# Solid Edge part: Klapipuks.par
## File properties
Author: Türk
Template: Iso Part.par
Last saved by: Türk
Revision: 10
Application: Solid Edge
Accuracy: 0,990
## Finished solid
Body 1: solid body, 13 faces, 23 edges, 12 vertices.
  Faces by surface: plane 7, cone 3, cylinder 3
  Edges by curve: line 14, circle 9
Bounding box of the edges (mm): 22.000 x 10.000 x 33.000, from (-11, 0, -11) to (11, 10, 22).
Cylindrical faces by radius (mm): R10 x1, R11 x2
Conical faces (half-angle, radius in mm at the cone's reference point): 45 deg R10 x1, 45 deg R10.5 x2
Planar faces by outward normal: +x 1, +y 1, -x 1, -y 2, oblique 2
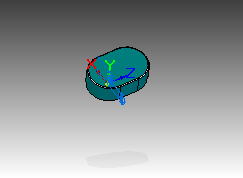
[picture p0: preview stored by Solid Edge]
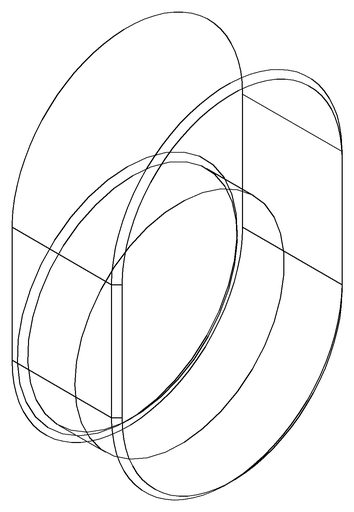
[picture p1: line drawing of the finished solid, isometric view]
